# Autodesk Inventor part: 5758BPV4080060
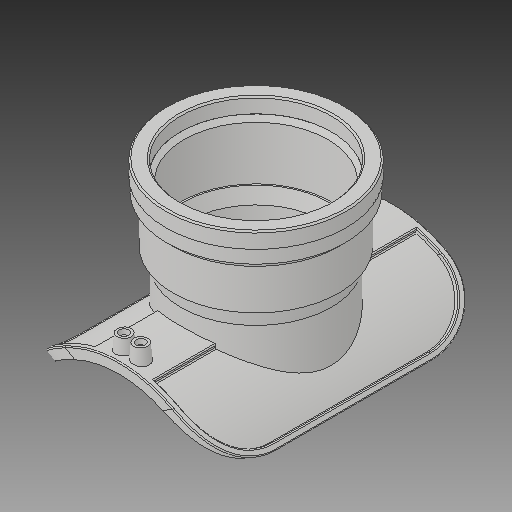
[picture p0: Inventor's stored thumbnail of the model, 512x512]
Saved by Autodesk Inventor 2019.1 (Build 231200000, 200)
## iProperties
Created: 2017-08
Part Number: 5758BPV4080060
Material: Generic
Description: PLASSON WASTEWATER SADDLE TEE 90 8''IPS x 6''PSM for PVC
Document SubType Name: Modeling
Designer: Кирилл
Density: 1 g/cm^3
Appearance: Default
Author: Кирилл
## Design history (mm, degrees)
derived "5758BP.ipt"
feature "Solid1::5758BP.ipt"
feature "Solid2::5758BP.ipt"
feature "Solid3::5758BP.ipt"
tag "TaggingFeature1"
body "Solid1"
other parameters: "d0" = 218.7, "d1" = 208.026, "d2" = 240.57, "d3" = 289.56, "d4" = 0, "d5" = 62.4078, "d6" = 6.364, "d7" = 30 deg, "d8" = 15 deg, "d10" = 0, "d11" = 142.155, "d38" = 1.0935, "d40" = 135.35, "d41" = 15, "d42" = 130.302, "d43" = 17.501, "d44" = 8.7505, "d46" = 5 deg, "d47" = 4, "d49" = 4, "d51" = 14, "d52" = 0, "d53" = 3, "d54" = 0, "d56" = 159.1, "d57" = 0.5, "d58" = 80.01, "d59" = 16.002, "d60" = 5.6007, "d61" = 40 deg, "d62" = 151.145, "d63" = 155.918, "d64" = 143.19, "d65" = 155 deg, "d66" = 124.968, "d67" = 189.992, "d68" = 188.09208, "d69" = 45 deg, "d70" = 174.546, "d72" = 7.723, "d75" = 0, "d77" = 0, "d78" = 1.591, "d81" = 37.4904, "d_" = 218.7, "B_" = 208.026, "H_" = 124.968, "L_" = 289.56, "d_1" = 159.1, "D_" = 189.992, "L_1" = 80.01, "d71" = 7.723
